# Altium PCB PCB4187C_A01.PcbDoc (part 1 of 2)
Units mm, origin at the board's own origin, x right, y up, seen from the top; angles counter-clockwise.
Board outline 30 x 45 mm, 4 copper layers (Top Layer, Signal Layer 2, Signal Layer 3, Bottom Layer), stack 1.6 mm thick; 73 components, 77 nets, 285 pads, 424 vias.
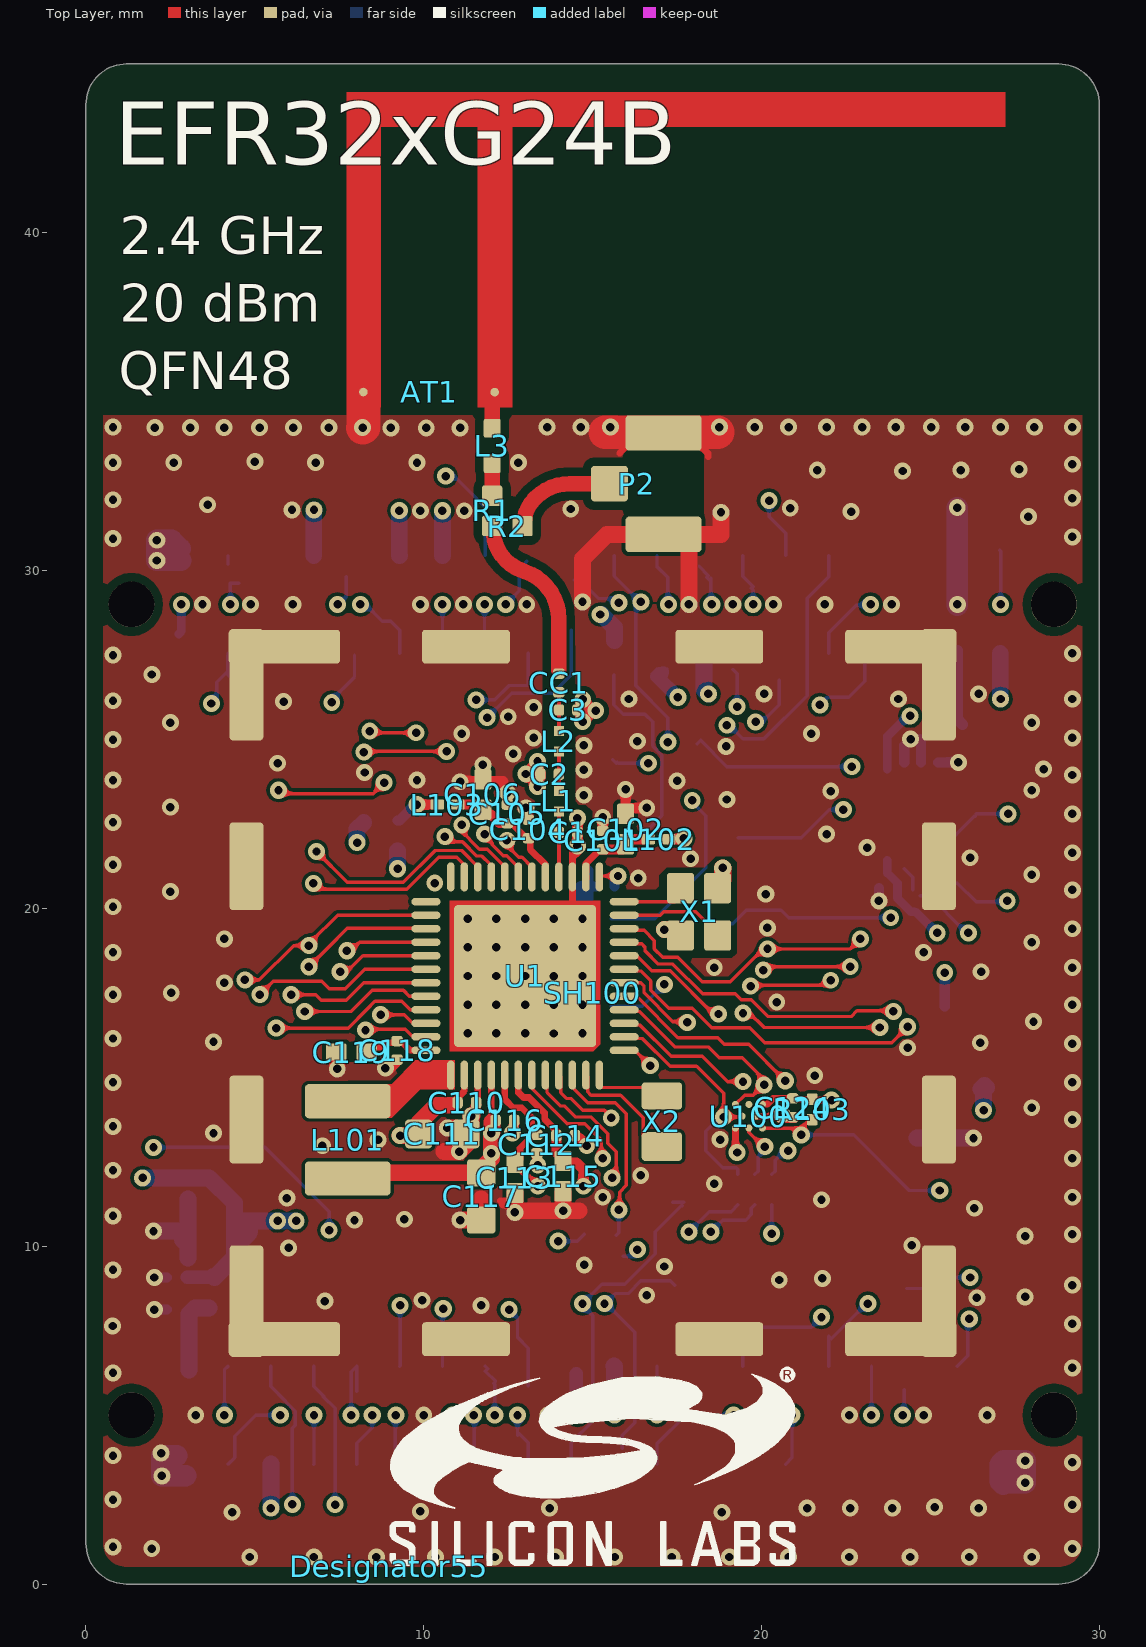
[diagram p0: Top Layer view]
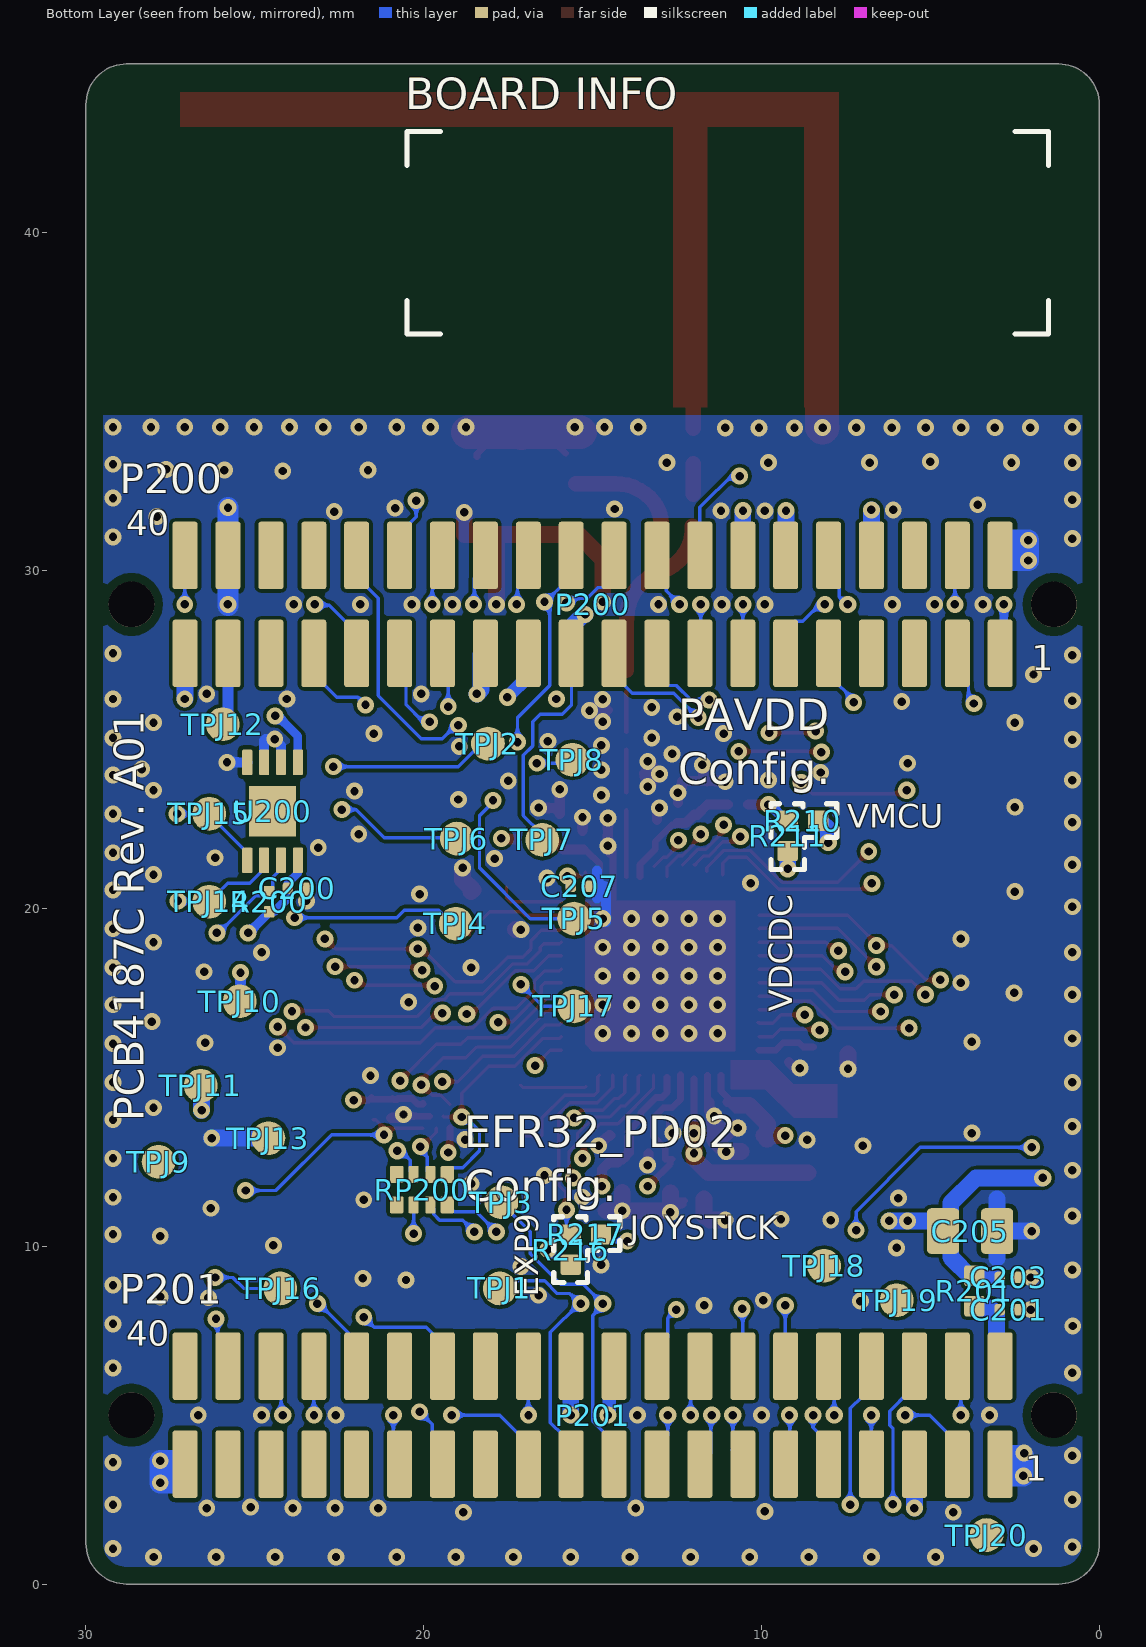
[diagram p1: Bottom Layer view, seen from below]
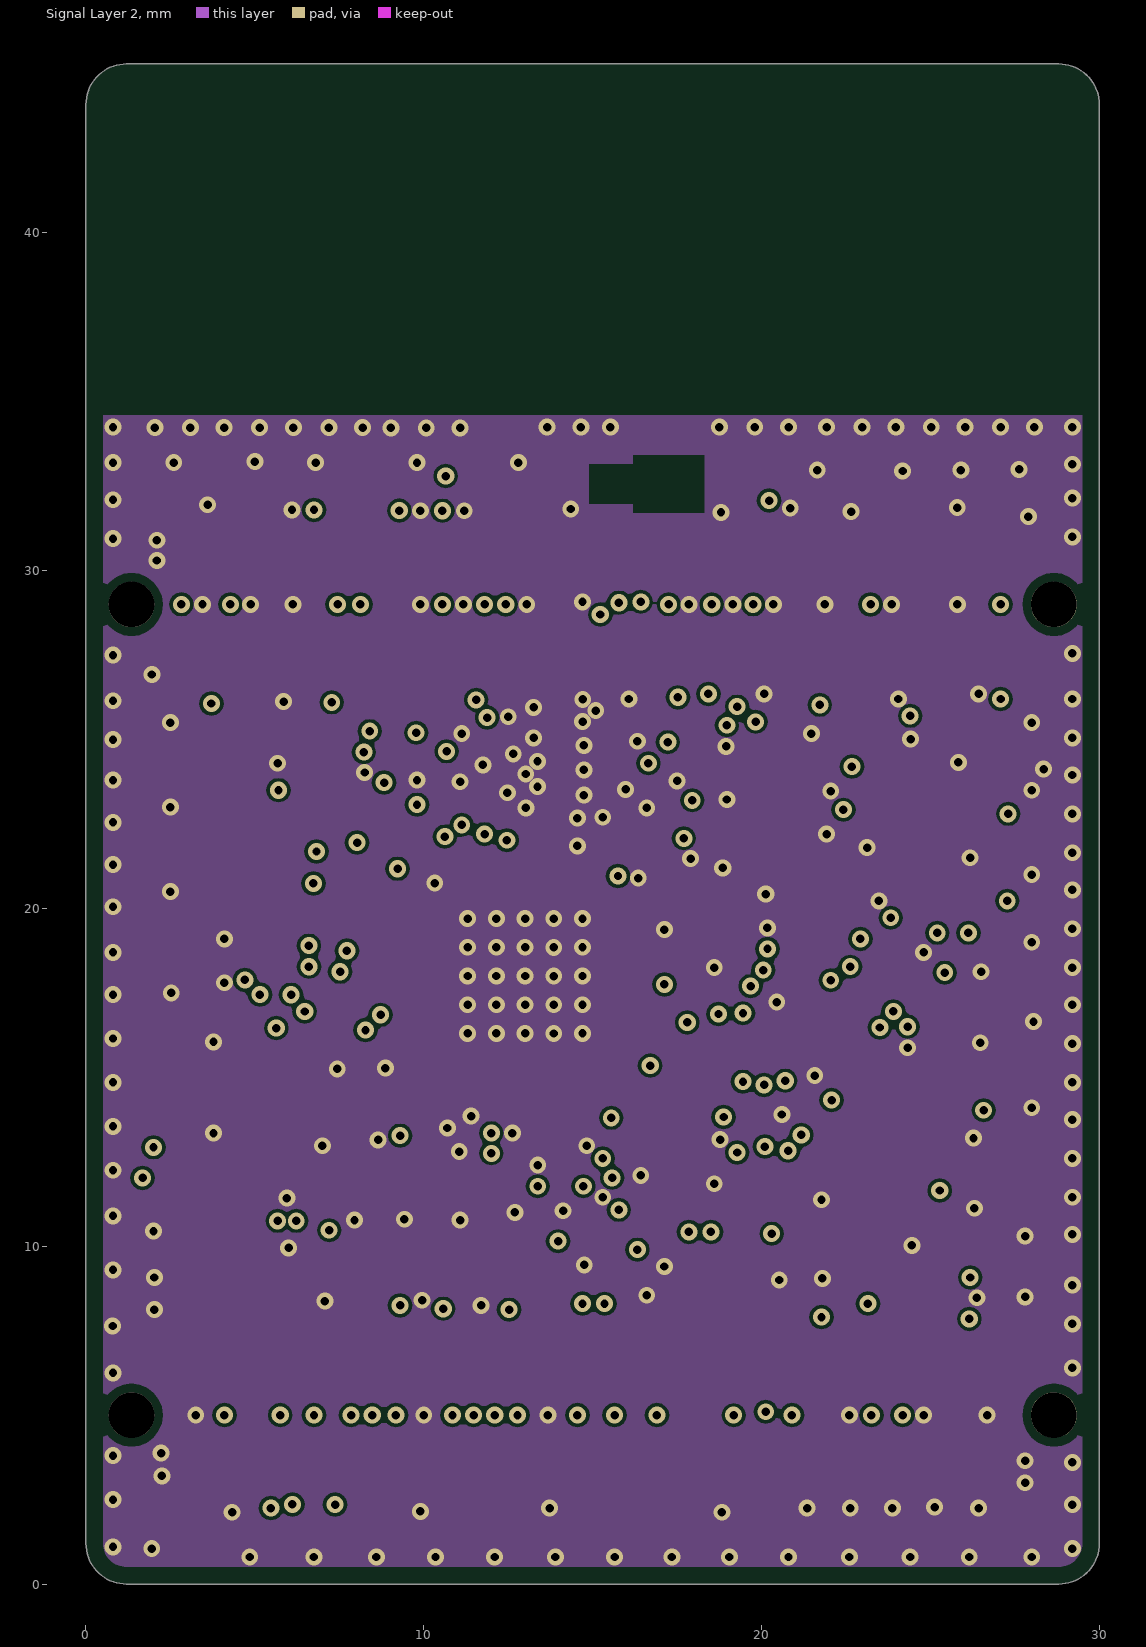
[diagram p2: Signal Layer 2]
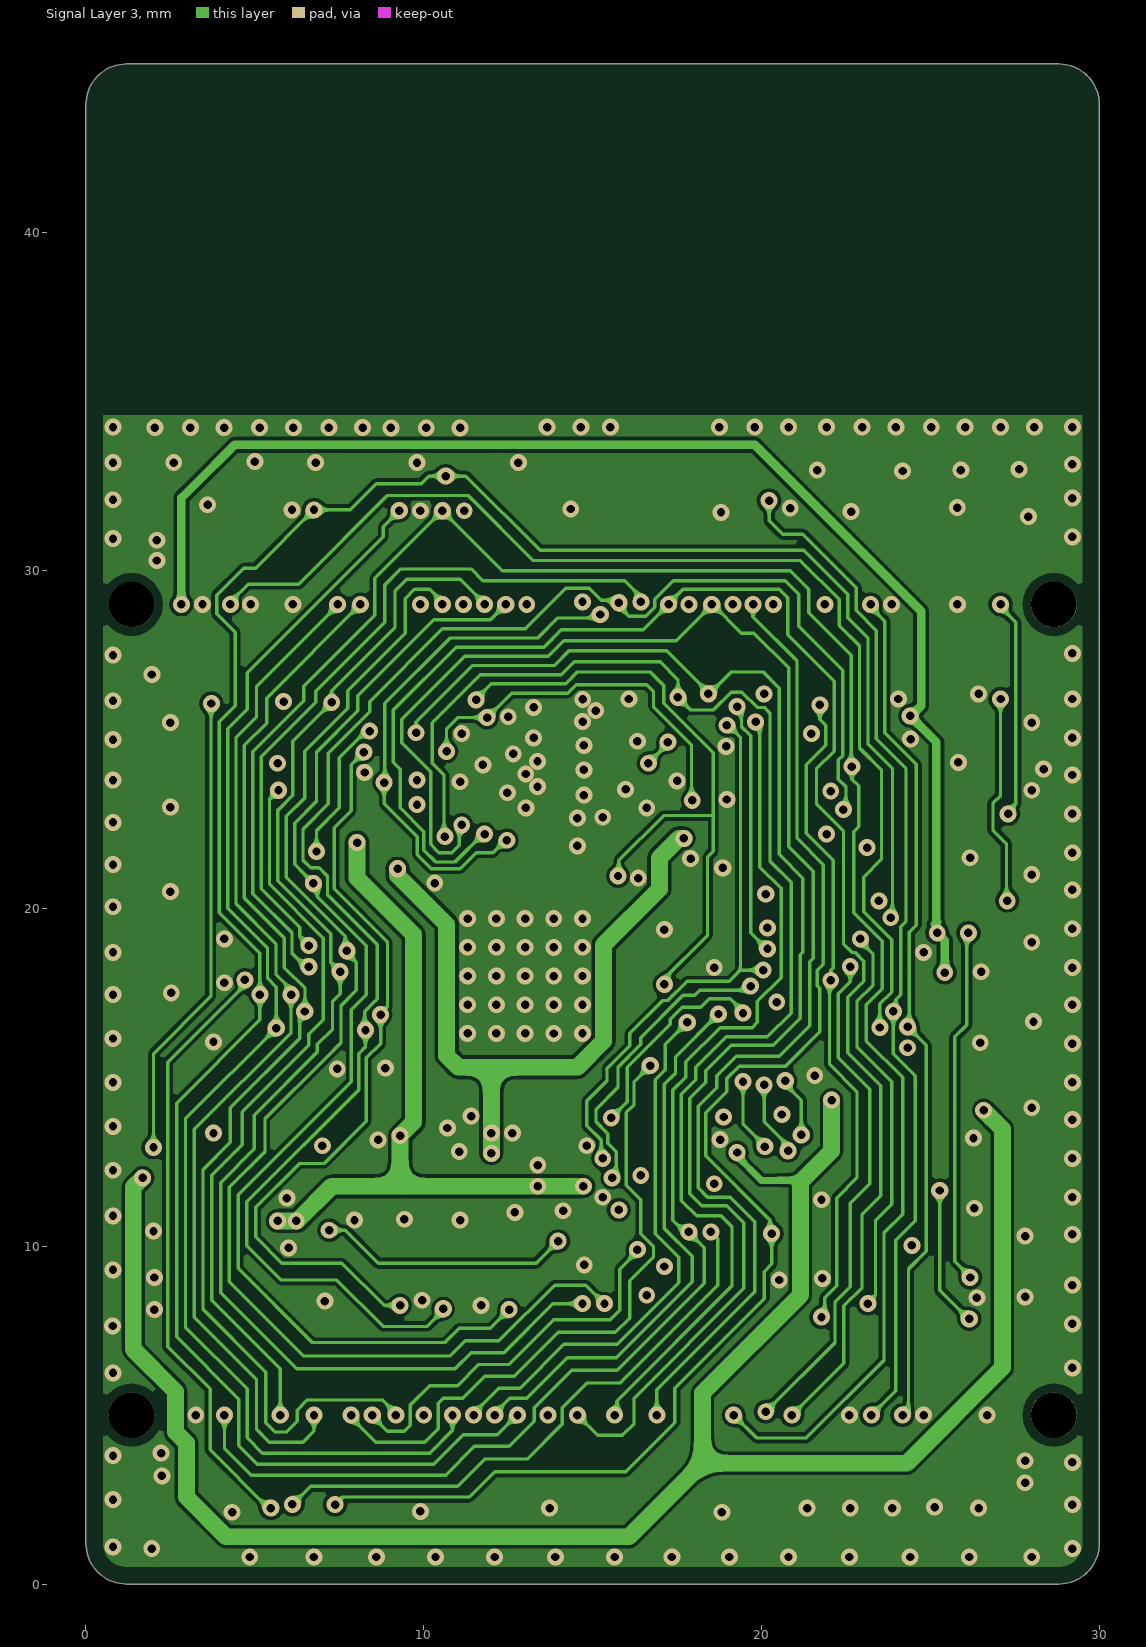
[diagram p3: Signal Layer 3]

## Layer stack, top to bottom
Top Solder: solder mask 0.0102, Solder Resist, Dk 3.5
Top Layer: signal copper 0.035
Dielectric 1: core 0.325, FR-4, Dk 4.2
Signal Layer 2: signal copper 0.018
Dielectric 3: prepreg 0.844, Dk 4.2
Signal Layer 3: signal copper 0.018
Dielectric 2: core 0.325, Dk 4.2
Bottom Layer: signal copper 0.035
Bottom Solder: solder mask 0.0102, Solder Resist, Dk 3.5

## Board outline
0,1.2 0,43.8 cw(c1.2,43.8) 1.2,45 28.8,45 cw(c28.8,43.8) 30,43.8 30,1.2 cw(c28.8,1.2) 28.8,0 1.2,0 cw(c1.2,1.2)

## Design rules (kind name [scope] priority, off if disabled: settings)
AcuteAngle [All] p1: minimum=7.00000000000000E+0001 checktracksonly=FALSE
BoardOutlineClearance [All] p1: gap=0.5
Clearance Clearance_50Ohm [InNetClass('50Ohm') vs InNet('GND')] p1: gap=0.254 except(0.15: Track-SMDPad; 0.2: SMDPad-SMDPad)
Clearance Clearance_to_Holes [InPadClass('NPTH')] p2: gap=0.254
Clearance Clerance_Polygon [InPolygon] p3: gap=0.1
Clearance Clearance_General [All] p4: gap=0.1
HoleToHoleClearance HoleToHoleClearance_ANT1toPAD [Incomponent ('ANT1') vs ISpad] p1: gap=0 allowstackedmicrovias=TRUE
HoleToHoleClearance HoleToHoleClearance_R1toR2_1 [Incomponent ('R1') vs Incomponent ('R2')] p2: gap=0 allowstackedmicrovias=TRUE
HoleToHoleClearance HoleToHoleClearance_U1toVIA_1 [InComponent ('U1') vs IsVia] p3: gap=0 allowstackedmicrovias=TRUE
HoleToHoleClearance [All] p4: gap=0.254 allowstackedmicrovias=TRUE
MinimumSolderMaskSliver [All] p1: minsoldermaskwidth=0.075
PolygonConnect Polygon_VIA_Connect [IsVia] p1: connectstyle=Direct reliefconductorwidth=0.254 reliefentries=4 polygonreliefangle="90 Angle" airgapwidth=0.254
PolygonConnect PolygonConnect_SH100 [InComponent('SH100')] p2: connectstyle=Direct reliefconductorwidth=0.254 reliefentries=4 polygonreliefangle="90 Angle" airgapwidth=0.127
PolygonConnect PolygonConnect_P1 [InComponent('P1')] p3: connectstyle=Relief reliefconductorwidth=0.3 reliefentries=4 polygonreliefangle="90 Angle" airgapwidth=0.127
PolygonConnect [All] p4: connectstyle=NoConnect reliefconductorwidth=0.2 reliefentries=4 polygonreliefangle="90 Angle" airgapwidth=0.125
RoutingVias [All] p1: holewidth=0.3 width=0.65 viastyle="Through Hole" minholewidth=0.25 minwidth=0.5 maxholewidth=1 maxwidth=1.5
ShortCircuit ShortCircuit_ANTtoPAD [InNet('50R_IFA') vs InNet('GND')] p1: allowed=TRUE
ShortCircuit ShortCircuit_R1toR2_1 [Incomponent ('R1') vs Incomponent ('R2')] p2: allowed=TRUE
ShortCircuit [All] p3: allowed=FALSE
SilkToSilkClearance [All] p1: silktosilkclearance=0.102
SilkToSolderMaskClearance [IsPad] p1: minsilkscreentomaskgap=0.102 clearancetoexposedcopper=TRUE
SolderMaskExpansion [All] p1: expansion=0.051
Width 50ohm [InNet('50R*')] p1: maxlimit=0.457 minlimit=0.124 preferedwidth=0.457
Width [All] p2: maxlimit=5.08 minlimit=0.1 preferedwidth=0.125
25 further rules are at their usual default settings.

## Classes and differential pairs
pad class NPTH: P200-M1 P200-M2 P201-M1 P201-M2
net class 50Ohm: 50R_IFA 50R_L3 50R_P2 50R_R1

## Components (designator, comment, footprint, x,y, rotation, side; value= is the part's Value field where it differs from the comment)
AT1 "INVERTED_F" EM358x_INVERTED_F 7.714,34.835 r0 top net-tie
C1 "2P3" C0201_L 14.275,22.25 r0 top
C2 "1P6" C0201_L 13.725,23.975 r180 top
C3 "N/A" C0201_L 14.275,25.875 r0 top
C101 "18P" C0201_L 15.3,22.025 r90 top
C102 "2U2" C0402_L 15.975,22.35 r90 top
C104 "0P5" C0201_L 13.1,22.35 r90 top
C105 "18P" C0201_L 12.475,22.8 r90 top
C106 "1U" C0402_L 11.75,23.375 r90 top
C110 "100N" C0201_L 11.275,14.25 r0 top
C111 "10U" C0603_L 10.55,13.325 r0 top
C112 "10N" C0201_L 13.35,13.025 r270 top
C113 "1U" C0402_L 12.7,12.025 r270 top
C114 "100N" C0201_L 14.2,13.275 r0 top
C115 "1U" C0402_L 14.125,12.075 r270 top
C116 "100N" C0201_L 12.4,13.725 r0 top
C117 "4U7" C0603_L 11.7,11.475 r270 top
C118 "100N" C0201_L 9.21,15.8 r270 top
C119 "1U" C0402_L 7.86,15.75 r180 top
C124 "100N" C0201_L 20.925,14.1 r270 top
C200 "100N" C0201_L 23.75,20.6 r180 bottom
C201 "100N" C0201_L 2.675,8.125 r180 bottom
C203 "100N" C0201_L 2.675,9.075 r180 bottom
C205 "10U" C0805_L 3.825,10.45 r180 bottom
C207 "100N" C0201_L 15.375,20.65 r180 bottom
CC1 "0R" C0201_L 14,26.675 r90 top
Designator39 "Comment" PCB_SPEC_4_LAYER -67.876,114.18 r0 top
Designator55 "Comment" LOGO_SILABS_W12.0 8.983,0.533 r0 top
L1 "2N9" COIL_0201_L 14,23.175 r90 top
L2 "1N2" COIL_0201_L 14,24.95 r90 top
L3 "0R" COIL_0402_L 12.025,33.693 r90 top
L101 "2U2" COIL_1008_L 7.75,13.15 r270 top
L102 "BLM03AG700SN1D" COIL_MUR_BLM03_0201 16.95,22.05 r180 top
L103 "BLM03AG700SN1D" COIL_MUR_BLM03_0201 10.7,23.075 r0 top
P2 "U.FL" HIROSE_U.FL-R-SMT-1 17.1,32.575 r90 top
P200 "SOCKET_WCON_2X20_1.27MM_SMD" SAM_SFC-120-T2-D-A-2X20_SNUM 15,29 r0 bottom locked
P201 "SOCKET_WCON_2X20_1.27MM_SMD" SAM_SFC-120-T2-D-A-2X20_SNUM 15,5 r0 bottom locked
R1 "0R" R0402_L 12.025,31.768 r90 top
R2 "0R" R0402_L 12.475,31.318 r0 top
R103 "330K" R0201_L 21.5,14.05 r90 top
R200 "10K" R0201_L 24.575,20.2 r270 bottom
R201 "0R" R0402_L 3.7,8.675 r90 bottom
R210 "0R" R0402_L 8.775,22.6 r180 bottom
R211 "0R" R0402_L 9.225,22.15 r90 bottom
R216 "0R" R0402_L 15.65,9.9 r270 bottom
R217 "0R" R0402_L 15.2,10.35 r180 bottom
RP200 "100R" RES_MNR04-8 20.05,11.675 r0 bottom
SH100 "RF_SHIELD_FRAME_BMI-S-202-F" shield_21x21mm 15,17.5 r90 top locked net-tie
TPJ1 "TPJ_SMD" TP_1.0_SMD 17.75,8.75 r90 bottom locked
TPJ2 "TPJ_SMD" TP_1.0_SMD 18.1,24.88 r90 bottom locked
TPJ3 "TPJ_SMD" TP_1.0_SMD 17.7,11.3 r90 bottom locked
TPJ4 "TPJ_SMD" TP_1.0_SMD 19.05,19.55 r90 bottom locked
TPJ5 "TPJ_SMD" TP_1.0_SMD 15.55,19.7 r90 bottom locked
TPJ6 "TPJ_SMD" TP_1.0_SMD 19.02,22.07 r90 bottom locked
TPJ7 "TPJ_SMD" TP_1.0_SMD 16.49,22.03 r90 bottom locked
TPJ8 "TPJ_SMD" TP_1.0_SMD 15.6,24.4 r90 bottom locked
TPJ9 "TPJ_SMD" TP_1.0_SMD 27.85,12.5 r90 bottom locked
TPJ10 "TPJ_SMD" TP_1.0_SMD 25.45,17.25 r90 bottom locked
TPJ11 "TPJ_SMD" TP_1.0_SMD 26.6,14.75 r90 bottom locked
TPJ12 "TPJ_SMD" TP_1.0_SMD 25.95,25.45 r90 bottom locked
TPJ13 "TPJ_SMD" TP_1.0_SMD 24.6,13.2 r90 bottom locked
TPJ14 "TPJ_SMD" TP_1.0_SMD 26.35,20.2 r90 bottom locked
TPJ15 "TPJ_SMD" TP_1.0_SMD 26.35,22.8 r90 bottom locked
TPJ16 "TPJ_SMD" TP_1.0_SMD 24.25,8.75 r90 bottom locked
TPJ17 "TPJ_SMD" TP_1.0_SMD 15.55,17.1 r90 bottom locked
TPJ18 "TPJ_SMD" TP_1.0_SMD 8.15,9.42 r90 bottom locked
TPJ19 "TPJ_SMD" TP_1.0_SMD 6,8.4 r90 bottom locked
TPJ20 "TPJ_SMD" TP_1.0_SMD 3.34,1.45 r90 bottom locked
U1 "EFR32MG24B020F1536IM48" QFN48_M040_6.0X6.0_EP_SL 13,18 r180 top
U100 "MX25R8035F" BGA8_M040_1.24X1.75_WLCSP 19.625,13.85 r270 top
U200 "M24C02" 8-TDFN 24.475,22.875 r0 bottom
X1 "39.000 MHz" KDS_DSX211SH_2016 18.15,19.9 r270 top
X2 "32.768 kHz" CRYSTAL_MCS_CM8V-T1A_Narrow 17.05,13.7 r270 top

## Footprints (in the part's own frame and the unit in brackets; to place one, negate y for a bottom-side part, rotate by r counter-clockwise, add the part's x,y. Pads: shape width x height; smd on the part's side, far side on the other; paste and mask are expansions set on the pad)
8-TDFN [mm] "TDFN8_M050_2.0x3.0_EP"
  rrect20% 0.3x0.75 smd mask+0.051: 1(-0.75,-1.45) 2(-0.25,-1.45) 3(0.25,-1.45) 4(0.75,-1.45) 5(0.75,1.45) 6(0.25,1.45) 7(-0.25,1.45) 8(-0.75,1.45)
  rect 1.4x1.5 smd mask+0.051: 9(0,0)
  body extent -1,-1.5 1,1.5, height 1
BGA8_M040_1.24X1.75_WLCSP [mm] "BGA, 8 pin. U100"
  round 0.21 smd mask+0.038: A1(-0.35,0.4) A3(0.35,0.4) B2(0,0.2) C1(-0.35,0) C3(0.35,0) D2(0,-0.2) E1(-0.35,-0.4) E3(0.35,-0.4)
  body extent -0.63,-0.89 0.63,0.88, height 0.52
C0201_L [mm] "Capacitor, Chip; 0.60 mm L X 0.30 mm W X 0.33 mm H body"
  rrect52% 0.31x0.34 smd: 1(-0.275,0) 2(0.275,0)
  body extent -0.3,-0.15 0.3,0.15, height 0.3
C0402_L [mm] "Chip Capacitor, 2-Leads, Body 1.0x0.5mm, IPC High Density"
  rrect20% 0.6x0.5 smd mask+0.051: 1(-0.45,0) 2(0.45,0)
  body extent -0.5,-0.25 0.5,0.25, height 0.6
C0603_L [mm] "Capacitor, 0603, High Density (C)"
  rrect25% 0.8x0.85 smd: 1(-0.7,0) 2(0.7,0)
  body extent -0.8,-0.4 0.8,0.4, height 0.95
C0805_L [mm] "Capacitor, 0805"
  rrect25% 0.95x1.35 smd: 1(-0.8,0) 2(0.8,0)
  body extent -1.1,-0.72 1.1,0.72, height 1.45
COIL_0201_L [mm] "JELF243C-0021"
  rrect10% 0.3x0.3 smd: 1(-0.3,0) 2(0.3,0)
  body extent -0.32,-0.17 0.32,0.17, height 0.33
COIL_0402_L [mm] "COIL_0402_L"
  rrect20% 0.55x0.5 smd mask+0.051: 1(-0.525,0) 2(0.525,0)
  body extent -0.5,-0.25 0.5,0.25, height 0.5
COIL_1008_L [mil] "Chip Inductors, 1008 (2520), Coilcraft (190207)"
  rrect25% 40x100 smd: 1(-45,0) 2(45,0)
  body extent -58,-55 57,55, height 80
COIL_MUR_BLM03_0201 [mm] "COIL_MUR_BLM03_0201"
  rrect25% 0.4x0.3 smd mask+0.051: 1(-0.3,0) 2(0.3,0)
  body extent -0.3,-0.15 0.3,0.15, height 0.95
CRYSTAL_MCS_CM8V-T1A_Narrow [mm] "Crystal MCS CM8V-T1A (2 pin)"
  rrect25% 0.8x1.2 smd mask+0.051: 1(-0.75,0)
  rrect25% 0.85x1.2 smd mask+0.051: 2(0.75,0)
  body extent -1,-0.6 1,0.6, height 0.6
EM358x_INVERTED_F [mil] "F-ANTENNA INVERSE 19.5 mm"
  round 10 smd paste-10 mask-10: 1(172.68,17.72) 2(19.69,17.85)
  Top Layer region: 0,367.2 767.72,367.2 767.72,327.07 193,327.07 193,0 153,0 153,327.07 40,327.07 40,0 20,0 0,0
HIROSE_U.FL-R-SMT-1 [mm] "COAX_HIROSE_U.FL_CL331-0471"
  rrect20% 1.05x1.1 smd mask+0.051: 1(0,1.6)
  rrect20% 1.05x2.25 smd mask+0.051: 2(-1.5,0) 3(1.5,0)
  Top Layer pour cut-out: -0.85,0.9 0.85,0.9 0.85,0.9 0.85,-1.2 -0.85,-1.2 -0.85,-1.2
  body extent -1.3,-1.55 1.3,1.3, height 0.9
KDS_DSX211SH_2016 [mm] "Copy of Silabs CE  X_KDS_DSX211SH_2.0X1.65-4"
  rrect20% 0.9x0.8 smd mask+0.051: 1(-0.7,-0.55) 2(0.7,-0.55) 3(0.7,0.55) 4(-0.7,0.55)
  body extent -1.07,-0.87 1.08,0.88, height 0.5
LOGO_SILABS_W12.0 [mm] "LOGO_SILABS_W12.0 (170217)"
  silkscreen extent 0.03,0.03 11.99,5.88
PCB_SPEC_4_LAYER [mm]
QFN48_M040_6.0X6.0_EP_SL [mm]
  rrect5% 4.2x4.2 smd paste-4.2 mask-4.2: 0(0,0)
  oval 0.86x0.22 smd paste+0 mask+0.06: 1(-2.935,2.2) 2(-2.935,1.8) 3(-2.935,1.4) 4(-2.935,1) 5(-2.935,0.6) 6(-2.935,0.2) 7(-2.935,-0.2) 8(-2.935,-0.6) 9(-2.935,-1) 10(-2.935,-1.4) 11(-2.935,-1.8) 12(-2.935,-2.2) 25(2.935,-2.2) 26(2.935,-1.8) 27(2.935,-1.4) 28(2.935,-1) 29(2.935,-0.6) 30(2.935,-0.2) 31(2.935,0.2) 32(2.935,0.6) 33(2.935,1) 34(2.935,1.4) 35(2.935,1.8) 36(2.935,2.2)
  oval 0.22x0.86 smd paste+0 mask+0.06: 13(-2.2,-2.935) 14(-1.8,-2.935) 15(-1.4,-2.935) 16(-1,-2.935) 17(-0.6,-2.935) 18(-0.2,-2.935) 19(0.2,-2.935) 20(0.6,-2.935) 21(1,-2.935) 22(1.4,-2.935) 23(1.8,-2.935) 24(2.2,-2.935) 37(2.2,2.935) 38(1.8,2.935) 39(1.4,2.935) 40(1,2.935) 41(0.6,2.935) 42(0.2,2.935) 43(-0.2,2.935) 44(-0.6,2.935) 45(-1,2.935) 46(-1.4,2.935) 47(-1.8,2.935) 48(-2.2,2.935)
  Top Layer region: 2.225,-2.225 -2.225,-2.225 -2.225,2.025 -2.025,2.225 2.225,2.225
  Top Layer pour cut-out: -2.505,-2.31 -2.31,-2.505 2.31,-2.505 2.505,-2.31 2.505,2.309 2.309,2.505 -2.31,2.505 -2.505,2.309
  body extent -3,-3 3,3, height 0.86
R0201_L [mm] "Resistor (Chip2PinSM127P600-8N) (170921)"
  rrect25% 0.34x0.32 smd: 1(-0.3,0) 2(0.3,0)
  body extent -0.32,-0.13 0.32,0.13, height 0.3
R0402_L [mm] "Chip Resistor, 2-Leads, Body 1.0x0.5mm, IPC High Density"
  rrect20% 0.6x0.6 smd mask+0.051: 1(-0.45,0) 2(0.45,0)
  body extent -0.5,-0.25 0.5,0.25, height 0.6
RES_MNR04-8 [mm] "Chip resistor network 8pin"
  rrect20% 0.4x0.5 smd mask+0.051: 1(-0.75,-0.45) 4(0.75,-0.45) 5(0.75,0.45) 8(-0.75,0.45)
  rrect20% 0.3x0.5 smd mask+0.051: 2(-0.25,-0.45) 3(0.25,-0.45) 6(0.25,0.45) 7(-0.25,0.45)
  body extent -1,-0.4 1,0.4, height 0.5
SAM_SFC-120-T2-D-A-2X20_SNUM [mm]
  rrect20% 0.74x2 smd mask+0.05: 1(-12.065,1.45) 2(-12.065,-1.45) 3(-10.795,1.45) 4(-10.795,-1.45) 5(-9.525,1.45) 6(-9.525,-1.45) 7(-8.255,1.45) 8(-8.255,-1.45) 9(-6.985,1.45) 10(-6.985,-1.45) 11(-5.715,1.45) 12(-5.715,-1.45) 13(-4.445,1.45) 14(-4.445,-1.45) 15(-3.175,1.45) 16(-3.175,-1.45) 17(-1.905,1.45) 18(-1.905,-1.45) 19(-0.635,1.45) 20(-0.635,-1.45) 21(0.635,1.45) 22(0.635,-1.45) 23(1.905,1.45) 24(1.905,-1.45) 25(3.175,1.45) 26(3.175,-1.45) 27(4.445,1.45) 28(4.445,-1.45) 29(5.715,1.45) 30(5.715,-1.45) 31(6.985,1.45) 32(6.985,-1.45) 33(8.255,1.45) 34(8.255,-1.45) 35(9.525,1.45) 36(9.525,-1.45) 37(10.795,1.45) 38(10.795,-1.45) 39(12.065,1.45) 40(12.065,-1.45)
  round 1.35 hole 1.35 unplated paste-5.563 mask-5.563: M1(13.652,0) M2(-13.652,0)
  body extent -14.29,-2.1 14.29,2.16, height 4.67
shield_21x21mm [mm] "RF_SHIELD wurth 3613205"
  rrect20% 1x3.3 smd paste+0 mask+0.05: 1(-10.25,-9.125) 1(-10.25,9.125) 1(10.25,-9.125) 1(10.25,9.125)
  rrect20% 1x2.6 smd paste+0 mask+0.05: 1(-10.25,-3.75) 1(-10.25,3.75) 1(10.25,-3.75) 1(10.25,3.75)
  rrect20% 3.3x1 smd paste+0 mask+0.05: 1(-9.125,-10.25) 1(-9.125,10.25) 1(9.125,-10.25) 1(9.125,10.25)
  rrect20% 2.6x1 smd paste+0 mask+0.05: 1(-3.75,10.25) 1(-3.75,-10.25) 1(3.75,10.25) 1(3.75,-10.25)
  body extent -13,-13 12.99,12.99, height 5.08
TP_1.0_SMD [mm] "Test Point, 1.0 mm, SMD"
  round 1 smd paste-0.501: 1(0,0)
  body extent -0.2,-0.2 0.2,0.2, height 0.01

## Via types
v1: diameter 0.5, hole 0.25, Top Layer to Bottom Layer, tented both sides, 347 vias
v2: diameter 0.508, hole 0.25, Top Layer to Bottom Layer, tented both sides, 77 vias

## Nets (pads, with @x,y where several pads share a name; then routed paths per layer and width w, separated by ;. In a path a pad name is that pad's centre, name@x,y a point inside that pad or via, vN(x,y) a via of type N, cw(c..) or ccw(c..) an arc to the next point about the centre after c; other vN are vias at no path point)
3V3: C200.1 P200.1 R200.2 TPJ10.1 U200.1 U200.8 | length 45.9
  Signal Layer 3 w0.254: v1(2.825,29.001) 2.825,32.15 3.15,32.475 4.404,33.729 19.796,33.729 24.725,28.8 24.725,26 24.529,25.804 v1@24.5,25.804 ; v1(24.4,25.7) 25.177,24.923 25.177,19.625 25.2,19.602 25.126,19.529 25.201,19.454 v1(25.201,19.276) 25.425,19.052 25.425,18.075 25.4,18.05 25.35,18.1 v1(25.425,18.1) v1@25.325,18.1
  Bottom Layer w0.254: P200.1@2.75,28.125 2.825,28.2 v1(2.825,29.001) ; U200.8@23.725,21.425 23.725,21.05 24.025,20.75 C200.1@24.025,20.625 ; U200.1@23.725,24.125 23.725,25.1 24.325,25.7 v1(24.4,25.7) ; C200.1@24.025,20.6 24.025,20.3 24.425,19.9 R200.2@24.525,19.9 ; R200.2@24.575,19.885 25.135,19.325 25.2,19.39 25.201,19.389 v1(25.201,19.276)
  Bottom Layer w0.305: TPJ10.1@25.425,17.1 v1(25.425,18.1)
5V: P200.37 TPJ12.1 | length 2.2
  Bottom Layer w0.33: P200.37@25.795,27.635 P200.37@25.795,27.55 25.795,25.605 TPJ12.1@25.95,25.45
50R_IFA: AT1.1 L3.2 | length 1.2
  Top Layer w0.457: L3.2@12.025,34.218 AT1.1@12.025,35.378
50R_L3: L3.1 R1.2 | length 0.9
  Top Layer w0.457: R1.2@12.025,32.268 L3.1@12.025,33.168
50R_P2: P2.1 R2.2 | length 3.2
  Top Layer w0.457: R2.2@12.975,31.4 cw(c14.001,31.4) 13.276,32.126 13.3,32.15 cw(c14.326,31.124) 14.326,32.575 P2.1@15.5,32.575
50R_R1: CC1.2 R1.1 R2.1 | length 5
  Top Layer w0.457: R2.1@12.05,31.318 ccw(c13.357,31.234) 12.924,29.998 ; 12.968,29.978 cw(c12.525,28.575) 13.996,28.575 ; 13.999,28.5 CC1.2@14.001,27.05
BOARD_ID_SCL: P200.39 TPJ14.1 U200.6 | length 10.5
  Signal Layer 3 w0.1: v1(27.075,26.2) 27.075,23.341 26.85,23.116 26.85,22.316 27.25,21.916 v1@27.25,20.275
  Bottom Layer w0.1: U200.6@24.825,21.075 25.15,20.75 25.8,20.75 TPJ14.1@26.35,20.2 v1@27.375,20.2
  Bottom Layer w0.5: P200.39@27.065,27.55 27.065,26.21 v1(27.075,26.2)
  other v1: 27.275,20.225
BOARD_ID_SDA: P200.40 TPJ15.1 U200.5 | length 10.7
  Signal Layer 3 w0.1: v1@27.075,28.925 27.526,28.474 27.526,23.101 v1@27.3,22.875
  Bottom Layer w0.102: U200.5@25.225,21.425 25.225,21.65 26.3,22.725 TPJ15.1@26.325,22.725 ; TPJ15.1@26.35,22.8 v1(27.3,22.8) ; P200.40@27.05,30.6 27.075,30.575 v1(27.075,29)
BOARD_ID_WP: R200.1 TPJ16.1 U200.7 | length 15
  Signal Layer 3 w0.1: v1(26.125,19.275) 26.075,19.225 26.075,16.55 25.725,16.2 25.725,9.55 26.175,9.1 v1(26.175,9.075)
  Bottom Layer w0.1: U200.7@24.225,21.175 24.475,20.925 R200.1@24.475,20.55 ; TPJ16.1@24.3,8.75 25.325,8.75 25.65,9.075 v1(26.175,9.075) ; R200.1@24.7,20.375 24.975,20.375 25.975,19.375 v1@26.025,19.375
EFR32_#RESET: C207.1 P200.17 TPJ17.1 U1.13 | length 25.5
  Top Layer w0.1: U1.13@15.2,20.935 15.221,20.956 U1.13@15.221,21.071 ; U1.13@15.241,21.051 15.15,20.96 v1(15.75,20.96)
  Signal Layer 3 w0.1: v1(11.55,26.175) 11.55,26.2 12,26.65 14.2,26.65 14.55,27 16.7,27 17.1,26.6 17.1,26.08 ; v1@15.725,21.118 15.775,21.168 15.775,21.425 17.1,22.75 18.55,22.75 ; 17.1,26.075 17.1,26.08 ; v2(17.126,17.751) 17.126,17.926 18.35,19.15 18.401,19.201 18.401,21.526 18.57,21.695 18.57,24.611 17.1,26.08
  Bottom Layer w0.1: v1(11.55,26.175) 12.1,26.175 12.525,26.6 13.05,26.6 13.095,26.645 P200.17@13.095,27.55 ; TPJ17.1@15.55,17.1 16.475,17.1 v2(17.126,17.751)
  Bottom Layer w0.3: C207.1@15.65,20.65 v1@15.65,20.96
EFR32_PA00: P200.22 P201.5 TPJ8.1 U1.26 | length 55.2
  Top Layer w0.1: v2(4.704,17.886) 5.136,17.886 6.151,18.901 v1(6.6,18.901) ; v1@6.675,19.025 7.45,19.8 8.975,19.8 U1.26@10.065,19.8
  Signal Layer 3 w0.1: v2(4.704,17.886) 4.704,17.771 4.725,17.75 2.425,15.45 2.425,7.025 3.675,5.775 3.675,3.975 5.4,2.25 v2(5.475,2.25) ; v1(6.6,18.901) 6.325,19.176 6.325,19.45 5.186,20.589 5.186,24.486 6.8,26.1 6.8,26.425 8.85,28.475 8.85,29.575 9.325,30.05 11.4,30.05 11.75,29.7 15.95,29.7 16.426,29.224 v1(16.426,29.076) ; v1(17.225,24.925) 17.2,24.925 17.237,24.888 v1(16.65,24.3) ; v1(16.65,24.3) 16.625,24.3 16.638,24.288 v1(16.65,24.3)
  Bottom Layer w0.1: TPJ8.1@15.6,24.4 15.7,24.3 15.725,24.325 15.75,24.3 v1(16.65,24.3) ; P200.22@15.635,30.45 15.635,29.84 16.375,29.1 v1@16.4,29.1 ; v1(16.426,29.076) 16.275,28.926 16.275,26.6 17.225,25.65 17.225,24.95 17.2,24.925 17.375,24.925 17.225,24.775 v1(17.225,24.925)
  Bottom Layer w0.5: v2(5.475,2.25) P201.5@5.475,3.55
EFR32_PA01: P200.14 P201.23 TPJ2.1 U1.27 | length 72.2
  Top Layer w0.1: v2(6.6,18.275) 7.15,18.825 7.74,19.415 10.05,19.415 U1.27@10.065,19.4
  Signal Layer 3 w0.1: v2(6.6,18.275) 6.5,18.275 6.1,18.675 6.1,19.275 4.939,20.436 4.939,24.639 6.449,26.149 6.449,26.574 8.55,28.675 8.55,29.775 v2(10.55,31.775) 12.325,30 20.85,30 21.4,29.45 21.4,28.75 22.65,27.5 22.65,24.223 v2(22.675,24.198) 22.675,23.826 22.875,23.626 22.875,22.425 22.725,22.275 22.725,19.875 23.575,19.025 23.575,17.625 23.1,17.15 23.1,16.075 24.175,15 24.175,10.95 23.625,10.4 23.625,6.625 21.325,4.325 19.85,4.325 v1(19.175,5)
  Bottom Layer w0.1: P201.23@16.905,3.55 16.905,4.155 17.75,5 v1(19.175,5) ; TPJ2.1@18.1,24.88 18.196,24.976 18.975,24.198 v2(22.675,24.198)
  Bottom Layer w0.5: v2(10.55,31.775) 10.555,31.77 P200.14@10.555,30.45
EFR32_PA02: P200.13 P201.21 TPJ1.1 U1.28 | length 49.9
  Top Layer w0.1: v2(7.725,18.75) 7.85,18.75 8.1,19 8.325,19 U1.28@10.065,19
  Signal Layer 3 w0.1: v2@7.675,18.975 7.675,19.175 5.93,20.92 5.93,22.724 6.475,23.269 6.475,24.65 7.75,25.925 7.75,26.45 9.45,28.15 9.45,29.175 9.725,29.45 10.175,29.45 10.55,29.075 v1(10.55,29) ; v2(7.725,18.75) 7.725,18.675 8,18.4 8,17.575 7.55,17.125 7.55,16.025 7.125,15.6 5.3,13.775 5.3,12.8 4.245,11.745 4.245,8.955 6.45,6.75 10.775,6.75 11.225,7.2 12.225,7.2 13.875,8.85 14.8,8.85 v1(15.35,8.3) ; v1(15.35,8.3) 15.4,8.25 15.45,8.3 v1(15.35,8.3)
  Bottom Layer w0.1: v1(10.55,29) 10.555,28.995 P200.13@10.555,27.55 ; v1(15.35,8.3) v1@15.375,8.3 ; v1@15.425,8.35 15.475,8.3 v1@15.4,8.3 ; P201.21@15.875,4.025 15.875,4.4 16.25,4.775 16.25,7.45 v1@15.4,8.3 ; TPJ1.1@17.426,8.85 17.301,8.975 16.425,8.975 16.05,8.6 15.675,8.6 v1@15.375,8.3 ; v1@15.375,8.3 v1@15.4,8.3
EFR32_PA03: P200.9 P200.15 P201.19 TPJ3.1 U1.29 | length 55.9
  Top Layer w0.1: v2(7.525,18.126) 7.726,18.126 8.2,18.6 U1.29@10.065,18.6
  Signal Layer 3 w0.1: 5.682,22.929 5.682,20.818 7.25,19.25 7.25,18.401 v2(7.525,18.126) 7.525,17.475 7.3,17.25 7.3,16.425 6.85,15.975 6.85,15.75 4.983,13.883 4.983,12.883 3.985,11.885 3.985,8.624 6.234,6.375 10.925,6.375 11.4,6.85 12.375,6.85 13.825,8.3 v2(14.7,8.3) ; 5.7,22.929 6.125,23.354 6.125,24.95 v1(7.275,26.1) 7.275,26.45 9.15,28.325 9.15,29.4 9.5,29.75 11.075,29.75 11.8,29.025 v2(11.8,29)
  Bottom Layer w0.1: v1(7.275,26.1) 7.275,26.175 7.95,26.85 P200.9@7.95,27.5 ; P200.15@11.775,27.625 11.825,27.675 11.8,27.7 v2(11.8,29) ; P201.19@14.365,3.55 14.365,4.19 15,4.825 15,7.95 v2@14.7,8.25 ; v2@14.675,8.275 v2@14.7,8.25 ; v2@14.688,8.287 v2(14.7,8.3) ; TPJ3.1@17.375,11.3 TPJ3.1@17.7,11.3 ; TPJ3.1@17.65,11.2 17.625,11.2 16.85,10.425 16.85,9.775 15.95,8.875 15.275,8.875 v2(14.7,8.3) ; v2@14.7,8.25 v2(14.7,8.3)
EFR32_PA04: P200.8 P200.16 P201.17 TPJ4.1 U1.30 | length 84.8
  Top Layer w0.1: v2(5.15,17.45) 5.55,17.85 6.979,17.85 7.204,17.625 7.675,17.625 8.25,18.2 U1.30@10.065,18.2
  Signal Layer 3 w0.1: v2(12.775,5) 12.75,5 12.175,4.425 11.175,4.425 10.3,3.55 5.075,3.55 4.525,4.1 4.525,5.475 2.685,7.315 2.685,14.235 5.15,16.7 v2(5.15,17.45) 5.15,18.67 3.948,19.873 3.948,25.525 4.423,26 4.423,28.177 3.875,28.725 3.875,29.275 4.675,30.075 5.025,30.075 v2(6.75,31.8) 7.825,31.8 8.6,32.575 9.925,32.575 10.15,32.8 v2(10.65,32.8) 11.243,32.8 13.443,30.6 21.25,30.6 22.55,29.3 22.55,28.608 23.15,28.008 23.15,24.875 23.875,24.15 v1@23.875,19.9
  Bottom Layer w0.1: v2@10.8,32.9 11.825,31.875 P200.16@11.825,30.45 ; v2(12.775,5) 12.775,4.4 12.825,4.45 13.095,4.18 P201.17@13.095,3.55 ; TPJ4.1@19.05,19.55 19.15,19.55 19.55,19.95 20.577,19.95 20.801,19.726 v1(23.824,19.726)
  Bottom Layer w0.5: P200.8@6.745,30.45 6.745,31.795 v2(6.75,31.8)
EFR32_PA05: P200.10 P201.7 U1.31 | length 37.2
  Top Layer w0.1: v2(6.071,17.446) 6.797,17.446 6.961,17.282 7.707,17.282 8.225,17.8 U1.31@10.065,17.8 U1.31@10.075,17.8
  Signal Layer 3 w0.1: v2(6.75,5) 6.75,4.525 6.425,4.2 5.425,4.2 5.05,4.575 5.05,6.05 3.205,7.895 3.205,13.459 6.071,16.325 v2(6.071,17.446) 6.071,17.604 5.625,18.05 5.625,18.95 4.443,20.132 4.443,25.075 5.05,25.682 5.05,26.575 7.45,28.975 v2(7.45,29)
  Bottom Layer w0.1: P201.7@6.745,3.55 6.75,3.555 v2@6.75,4.775 ; v2(7.45,29) 7.475,29 7.7,29.225 P200.10@7.7,29.825
EFR32_PA06: P200.11 P201.11 U1.32 | length 41.1
  Top Layer w0.1: v2(6.475,16.95) 7.85,16.95 8.475,17.575 9.4,17.575 9.575,17.4 U1.32@10.065,17.4
  Signal Layer 3 w0.1: v2(8.125,29) 5.35,26.225 5.35,25.484 4.691,24.825 4.691,20.309 5.875,19.125 5.875,18.25 6.486,17.639 6.486,16.95 v2(6.475,16.95) 6.325,16.8 6.325,16.15 4.275,14.1 4.275,13.075 3.465,12.265 3.465,8.135 5.325,6.275 5.325,4.775 5.6,4.5 5.925,4.5 6.25,4.825 6.25,5.15 6.55,5.45 8.775,5.45 9.175,5.05 v2(9.175,5)
  Bottom Layer w0.1: v2(8.125,29) 8.275,29 8.775,28.5 9.025,28.5 9.285,28.24 P200.11@9.285,27.55 ; P201.11@9.16,3.5 v2@9.16,4.9 ; v2@9.16,4.9 9.285,4.96 9.245,5 v2(9.175,5) 9.235,5 v2@9.16,4.9
EFR32_PA07: P200.12 P201.13 U1.33 | length 47
  Top Layer w0.1: v2(5.634,16.459) 7.762,16.459 8.319,17.016 8.319,17.018 8.556,17.255 9.349,17.255 9.6,17.004 10.061,17.004 U1.33@10.065,17
  Signal Layer 3 w0.1: v2(9.275,31.777) 8.8,31.301 8.8,31 4.775,26.975 4.775,25.9 4.195,25.32 4.195,20.005 5.375,18.825 5.375,17.929 5.634,17.67 v2(5.634,16.459) 2.945,13.77 2.945,7.605 4.775,5.775 4.775,4.325 5.225,3.875 10.175,3.875 10.851,4.551 v2(10.851,5)
  Bottom Layer w0.1: v2@9.275,31.68 9.37,31.775 9.368,31.777 v2(9.275,31.777) ; P201.13@10.555,3.55 10.5,3.605 10.875,3.98 10.851,4.004 v2(10.851,5)
  Bottom Layer w0.5: v2@9.275,31.68 9.275,30.46 P200.12@9.285,30.45
EFR32_PA08: P200.19 P201.12 TPJ5.1 U1.34 | length 49.6
  Top Layer w0.1: v1(8.226,24.626) 8.124,24.626 8.1,24.65 v1(10.675,24.65) ; v2(8.723,16.851) 9.424,16.851 9.675,16.6 U1.34@10.065,16.6 ; U1.34@10.065,16.625 U1.34@10.115,16.625
  Signal Layer 3 w0.1: v1(8.226,24.626) 7.85,24.25 7.85,22.885 7.35,22.385 7.35,20.583 8.925,19.008 8.925,17.1 8.825,17 8.7,16.874 v2(8.723,16.851) 8.723,15.998 8.3,15.575 8.3,13.7 7.05,12.45 6.325,12.45 5.025,11.15 5.025,10.275 5.8,9.5 7.575,9.5 8.825,8.25 v2(9.3,8.25) ; v1(10.675,24.65) 10.675,25.325 11.001,25.651 v1(11.876,25.651) 11.878,25.651 11.95,25.724 11.95,25.725 12.6,26.375 14.263,26.375 14.513,26.625 16.6,26.625 16.8,26.425 16.8,25.975 17.925,24.85 17.925,23.225 v1(17.95,23.2)
  Bottom Layer w0.1: P201.12@9.285,6.45 9.3,6.465 v2(9.3,8.25) ; v1(11.876,25.651) 11.878,25.651 12.601,26.375 13.825,26.375 14.365,26.915 P200.19@14.365,27.55 P200.19@14.365,28.24 ; TPJ5.1@15.55,19.7 16.841,19.7 18.35,21.209 18.35,22.745 17.95,23.145 v1(17.95,23.2)
EFR32_PA09: P200.20 P201.14 TPJ6.1 U1.35 | length 58.1
  Top Layer w0.1: v2(8.275,16.401) v2@8.33,16.346 ; v2@8.275,16.45 8.3,16.425 9.45,16.425 9.675,16.2 U1.35@10.065,16.2 U1.35@10.061,16.196
  Signal Layer 3 w0.1: v2(10.575,8.15) 10.575,8.1 10.1,7.625 8.8,7.625 7.425,9 5.775,9 4.765,10.01 4.765,11.315 8.075,14.625 8.075,15.7 8.275,15.9 8.275,16.4 8.25,16.375 8.25,16.949 8.556,17.255 8.558,17.255 8.625,17.322 8.625,18.933 7.15,20.408 7.15,20.95 6.9,21.2 6.65,21.2 6.425,21.425 6.425,22.35 7.175,23.1 7.175,24.6 8.4,25.825 8.4,26.125 10.553,28.278 13.025,28.278 ; 13.025,28.3 14.2,29.475 14.9,29.475 15.134,29.241 15.25,29.125 15.727,29.125 v2@15.788,29.064 ; v1(22.425,22.925) v1@22.5,22.925 ; v2@15.788,29.064 v2(15.776,29.051) 15.788,29.051 v2@15.795,29.058 ; v2@15.788,29.064 15.795,29.07 v2@15.795,29.058 ; v2@15.788,29.064 v2@15.795,29.058 ; v2@15.795,29.058 15.813,29.076 15.815,29.075 15.796,29.056 v2@15.795,29.058 ; v2@15.795,29.058 15.795,28.93 16.075,28.65 16.566,28.65 16.835,28.919 16.835,29.15 17.384,29.7 20.7,29.7 21.1,29.3 21.1,28.35 22.4,27.05 22.4,24.525 22.271,24.396 22.271,23.828 22.5,23.599 v1@22.5,22.925 ; v1@22.5,22.925 22.525,22.925 22.5,22.9 v1@22.5,22.925
  Bottom Layer w0.1: P201.14@10.555,6.45 v2@10.555,8.13 ; P200.20@14.45,29.725 14.675,29.5 14.85,29.5 15.175,29.175 15.677,29.175 v2@15.795,29.058 ; v2(15.776,29.051) 15.788,29.051 v2@15.795,29.058 ; TPJ6.1@19.305,22.095 21.17,22.095 22,22.925 v1(22.425,22.925) ; v2@15.795,29.058 15.813,29.076 15.815,29.075 15.796,29.056 v2@15.795,29.058
EFR32_PB00: P200.18 P201.18 U1.23 | length 44.5
  Top Layer w0.1: v2(6.735,20.74) 6.904,20.571 9.496,20.571 10.44,21.515 10.972,21.515 11.15,21.337 U1.23@11.15,21
  Signal Layer 3 w0.1: v2(12.426,29) 11.976,28.55 10.3,28.55 8.05,26.3 8.05,25.85 6.825,24.625 6.825,23.175 6.177,22.527 6.177,21.307 6.484,21 6.48,20.995 v2(6.735,20.74) 6.85,20.625 6.85,20.346 8.3,18.896 8.3,17.45 7.85,17 7.85,14.875 4.505,11.53 4.505,9.345 6.7,7.15 10.625,7.15 11.05,7.575 11.975,7.575 v1(12.525,8.125)
  Bottom Layer w0.1: v2@12.426,28.926 v2(12.426,29) 12.825,29.4 12.825,29.8 13.05,30.025 12.925,30.15 P200.18@13.05,30.275 ; v1(12.525,8.125) 12.775,7.875 12.775,7.3 13.095,6.98 P201.18@13.095,6.45 P201.18@13.095,5.87
EFR32_PB01: P200.25 P201.20 U1.22 | length 56.4
  Top Layer w0.1: v1(6.825,21.686) 7.74,20.771 9.396,20.771 10.34,21.715 11.119,21.715 11.625,21.209 U1.22@11.625,21.1 ; v1(8.4,25.25) 8.45,25.2 v1(9.775,25.2)
  Signal Layer 3 w0.1: v1(6.825,21.686) 6.825,22.3 7.5,22.975 7.5,24.466 8.284,25.25 v1(8.4,25.25) ; v1(9.775,25.2) 9.775,25.525 11.441,27.191 13.866,27.191 14.3,27.625 17.2,27.625 v2@18.5,26.325 ; v2(14.55,5) 15.15,4.4 15.875,4.4 16.225,4.75 16.225,5.5 19.475,8.75 19.475,10.7 18.975,11.2 18.225,11.2 17.875,11.55 17.875,14.375 18.35,14.85 18.35,15.2 19.1,15.95 20.35,15.95 21.15,16.75 21.15,18.625 21.225,18.7 21.225,20.9 20.525,21.6 20.525,26.525 20.05,27 19.1,27 18.325,26.225 v2@18.225,26.325 ; v2@18.325,26.275 18.25,26.35 v2@18.475,26.35
  Bottom Layer w0.4: v2@14.515,5 P201.20@14.515,6.225
  Bottom Layer w0.5: P200.25@18.3,27.525 18.3,26.475 v2(18.425,26.35)
EFR32_PB02: P200.23 P201.22 U1.21 | length 45.7
  Top Layer w0.1: v1@10.55,22.075 10.655,21.97 11.147,21.97 11.566,21.551 11.724,21.551 11.95,21.325 11.95,21.293 U1.21@12,21.293
  Signal Layer 3 w0.1: v1(10.626,22.126) 10.626,22.198 10.6,22.224 10.6,23.95 10.248,24.302 10.248,25.498 11.669,26.919 14.069,26.919 14.45,27.3 17,27.3 17.525,26.775 v2(17.525,26.25) 17.9,25.875 18.575,25.875 19.1,26.4 19.418,26.4 19.868,25.95 20.075,25.95 20.25,25.775 20.25,21.4 20.875,20.775 20.875,16.9 20.175,16.2 18.95,16.2 18.05,15.3 18.05,14.925 17.625,14.5 17.625,11.35 18.075,10.9 18.8,10.9 19.125,10.575 19.125,8.825 15.725,5.425 v2@15.725,5.05
  Bottom Layer w0.1: P200.23@17.05,26.95 P200.23@17.2,27.1
  Bottom Layer w0.4: P200.23@17.05,26.95 16.975,26.95 16.9,26.875 v2(17.525,26.25)
  Bottom Layer w0.5: P201.22@15.635,6.45 15.65,6.435 v2(15.65,5)
EFR32_PB03: P200.26 P201.24 U1.20 | length 51
  Top Layer w0.1: v1@11.075,22.5 11.075,22.325 11.649,21.751 11.882,21.751 U1.20@12.338,21.295
  Signal Layer 3 w0.1: v1@11.05,22.525 11.05,21.875 10.825,21.65 10.45,21.65 10.204,21.896 10.204,24.046 9.35,24.9 9.35,25.6 11.212,27.462 13.687,27.462 14.15,27.925 17.475,27.925 18.525,28.975 v2(18.525,29) ; v2(16.9,5) 16.9,5.75 19.8,8.65 19.8,10.725 19.075,11.45 18.4,11.45 18.125,11.725 18.125,14.15 18.671,14.696 18.671,15.046 19.25,15.625 20.525,15.625 21.426,16.526 21.426,18.426 21.525,18.525 21.525,21.1 20.8,21.825 20.8,27.125 19.775,28.15 19.4,28.15 18.55,29 v2@18.538,28.987
  Bottom Layer w0.1: v2(16.9,5) 16.905,5.005 P201.24@16.905,6.45 ; P200.26@18.15,30.125 18.425,29.85 18.375,29.8 18.45,29.725 18.5,29.775 18.5,29.025 v2(18.525,29)
  other v1: 11.125,22.475
EFR32_PB04: P200.24 P201.29 U1.19 | length 52.6
  Top Layer w0.1: v1@11.85,22.175 11.85,22.1 12.025,21.925 12.025,21.891 12.353,21.562 12.462,21.562 12.8,21.225 U1.19@12.8,20.935
  Signal Layer 3 w0.1: v1@11.775,22.225 10.925,21.375 10.35,21.375 10.004,21.721 10.004,22.271 9.3,22.975 9.3,24.125 9.1,24.325 9.1,25.875 10.959,27.734 13.559,27.734 14.075,28.25 16.5,28.25 v1(17.25,29) v1@17.225,29 ; v2(20.9,5) v2@21.1,5 ; v2@20.912,5.012 22.438,6.538 22.438,8.238 22.975,8.775 22.975,10.95 23.525,11.5 23.525,14.75 22.55,15.725 22.55,17.375 23.026,17.851 23.026,18.442 22.772,18.696 22.679,18.696 22.425,18.95 22.425,22.3 21.625,23.1 21.625,24.134 22.15,24.659 22.15,26.725 20.775,28.1 20.775,29.2 20.525,29.45 17.675,29.45 v1@17.225,29 ; v1@17.225,29 17.187,28.962 17.15,29 v1@17.225,29
  Bottom Layer w0.1: P200.24@16.905,30.45 16.905,30.12 17.225,29.8 17.225,29.025 v1(17.25,29) ; P201.29@20.715,3.55 20.9,3.735 20.9,4.95 v2(20.9,5)
  other v1: 11.8,22.2
EFR32_PB05: P200.21 P201.3 TPJ7.1 U1.18 | length 51.3
  Top Layer w0.1: v2(5.7,23.5) 5.8,23.4 8.499,23.4 v2(8.825,23.726) ; v1(12.461,22.02) 12.461,21.864 12.81,21.515 12.91,21.515 U1.18@13.175,21.25
  Signal Layer 3 w0.1: v2(5.7,23.5) 5.434,23.234 5.434,20.716 7.029,19.121 7.029,16.704 6.6,16.275 6.6,15.95 4.625,13.975 4.625,13 3.725,12.1 3.725,8.4 5.75,6.375 v2(5.75,5) ; v2@8.825,23.725 8.825,23.1 9.804,22.121 9.804,21.596 10.225,21.175 11.075,21.175 11.55,21.65 12.05,21.65 12.416,22.016 v1@12.466,22.016 ; v2(8.825,23.726) v2@8.94,23.726 ; v2@8.85,23.751 8.85,26.075 10.781,28.006 13.375,28.006 13.969,28.6 15.224,28.6 15.3,28.676 15.232,28.744 15.226,28.738 v2(15.226,28.701)
  Bottom Layer w0.1: P201.3@4.205,3.55 4.4,3.745 4.4,4.375 5.025,5 v2(5.75,5) ; P200.21@15.635,26.911 15.625,26.901 15.625,26.025 15.9,25.75 16.55,25.75 16.775,25.525 16.775,24.809 17.05,24.534 17.05,22.75 16.525,22.225 TPJ7.1@16.525,22.05
  Bottom Layer w0.5: v2(15.226,28.701) 15.266,28.701 15.65,28.317 P200.21@15.65,27.925
EFR32_PC00: P201.10 U1.1 | length 22.2
  Top Layer w0.1: U1.1@15.935,15.8 16.25,15.8 v2(16.703,15.347)
  Signal Layer 3 w0.1: v2@7.85,5.047 v2(7.85,5) 7.85,4.925 8.575,4.2 10.025,4.2 10.425,4.6 10.425,5.35 10.575,5.5 11.15,5.5 11.8,6.15 12.675,6.15 13.975,7.45 15.675,7.45 16.1,7.875 16.1,8.975 16.8,9.675 16.8,10 16.425,10.375 16.425,11.375 16,11.8 16,13.96 16.225,14.185 16.225,14.875 v2@16.7,15.35
  Bottom Layer w0.1: v2(7.85,5) 7.85,6.285 P201.10@8.015,6.45 P201.10@8.015,5.71
EFR32_PC01: RP200.1 U1.2 U100.D2 | length 7.5
  Top Layer w0.1: U1.2@15.935,16.2 15.985,16.15 16.475,16.15 17.3,15.325 18.075,15.325 18.876,14.524 v2(18.876,13.826) U100.D2@19.399,13.826 ; U100.D2@19.4,13.825 U100.D2@19.425,13.85
  Bottom Layer w0.1: v2(18.876,13.826) 18.776,13.826 18.35,13.4 18.35,12.825 18.85,12.325 19.25,12.325 19.3,12.275 RP200.1@19.3,12.125
EFR32_PC02: RP200.2 U1.3 U100.C3 | length 8.3
  Top Layer w0.1: U1.3@15.935,16.6 15.985,16.55 16.4,16.55 17.325,15.625 18.25,15.625 19,14.875 v1(19.45,14.875) ; U100.C3@19.625,13.5 19.625,13.375 v2@20.1,12.9
  Signal Layer 3 w0.1: v1(19.45,14.875) 19.45,13.625 20.1,12.975 v2(20.1,12.95)
  Bottom Layer w0.1: RP200.2@19.8,12.125 19.9,12.225 19.9,12.65 20.176,12.926 20.152,12.95 v2(20.1,12.95)
EFR32_PC03: RP200.3 U1.4 U100.E1 | length 9.4
  Top Layer w0.1: U1.4@15.935,17 16.25,17 16.3,16.95 16.375,16.95 17.425,15.9 18.425,15.9 18.75,15.575 19.425,15.575 20.076,14.924 v2(20.076,14.776) ; U100.E1@19.225,14.2 19.5,14.475 19.75,14.475 v2@20.037,14.762
  Signal Layer 3 w0.1: v2(20.076,14.776) 20.076,13.689 20.784,12.981 v2(20.784,12.828)
  Bottom Layer w0.1: RP200.3@20.3,12.125 20.4,12.225 20.4,12.55 20.731,12.881 v2(20.784,12.828)
EFR32_PC04: P201.38 R103.1 U1.5 U100.A3 | length 20.4
  Top Layer w0.1: U1.5@15.935,17.4 15.985,17.35 16.35,17.35 17.525,16.175 18.7,16.175 18.9,15.975 19.625,15.975 20.663,14.937 20.627,14.901 v2(20.701,14.901) ; U100.A3@20.025,13.5 20.025,13.495 21.16,13.495 21.415,13.75 R103.1@21.5,13.75
  Signal Layer 3 w0.1: v2(20.701,14.901) v2@20.596,14.901 ; v2(21.176,13.296) 21.176,14.32 v2@20.625,14.871 ; v2(25.275,11.65) 25.275,8.7 26.125,7.85 v2(26.15,7.85) ; v2@20.596,14.901 20.524,14.901 20.494,14.871 v2@20.625,14.871 ; v2@20.596,14.901 v2@20.625,14.871
  Bottom Layer w0.1: v2(21.176,13.296) 22.729,13.296 24.375,11.65 v2(25.275,11.65) ; P201.38@25.795,6.45 26.1,6.755 26.1,7.95 26.15,7.9 v2(26.15,7.85)
EFR32_PC05: P201.15 U1.6 | length 20.7
  Top Layer w0.1: U1.6@15.935,17.8 16.425,17.8 16.522,17.703 16.522,17.501 17.373,16.65 17.775,16.65 v2(17.8,16.625)
  Signal Layer 3 w0.1: v2(11.475,5) 11.475,5.05 12.225,5.8 12.85,5.8 14.15,7.1 15.725,7.1 17.55,8.925 17.55,9.675 16.85,10.375 16.85,14.922 17.15,15.222 17.15,15.975 v2(17.8,16.625)
  Bottom Layer w0.1: v2(11.475,5) 11.3,5 11.438,5.137 11.5,5.075 11.5,3.875 P201.15@11.825,3.55
EFR32_PC06: P200.31 P201.36 U1.7 | length 37.7
  Top Layer w0.1: U1.7@15.935,18.2 15.985,18.15 16.425,18.15 16.722,17.853 16.722,17.584 17.255,17.05 17.95,17.05 18.529,16.471 19.654,16.471 20.1,16.025 23.85,16.025 v2@24.35,16.525
  Signal Layer 3 w0.1: v2@23.226,28.926 23.65,28.503 23.65,25.2 24.575,24.275 24.575,19.5 24.375,19.3 24.375,16.55 v2(24.325,16.5) 24.871,15.954 24.871,9.848 24.35,9.327 24.35,5.174 v2(24.176,5)
  Bottom Layer w0.1: P200.31@21.985,27.55 21.985,28.16 22.8,28.975 v2@23.2,28.975 ; v2(24.176,5) 24.225,5.049 P201.36@24.225,5.75
  other v2: 23.226,29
